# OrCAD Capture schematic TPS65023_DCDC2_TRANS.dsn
size Custom; title: TPS65023x Power Management IC (PMIC) With 3 DC/DCs,; rev: 1.0; note: Datasheet: SLVS670L     EVM: SLVU193; note: Synchronous Step Down Converter
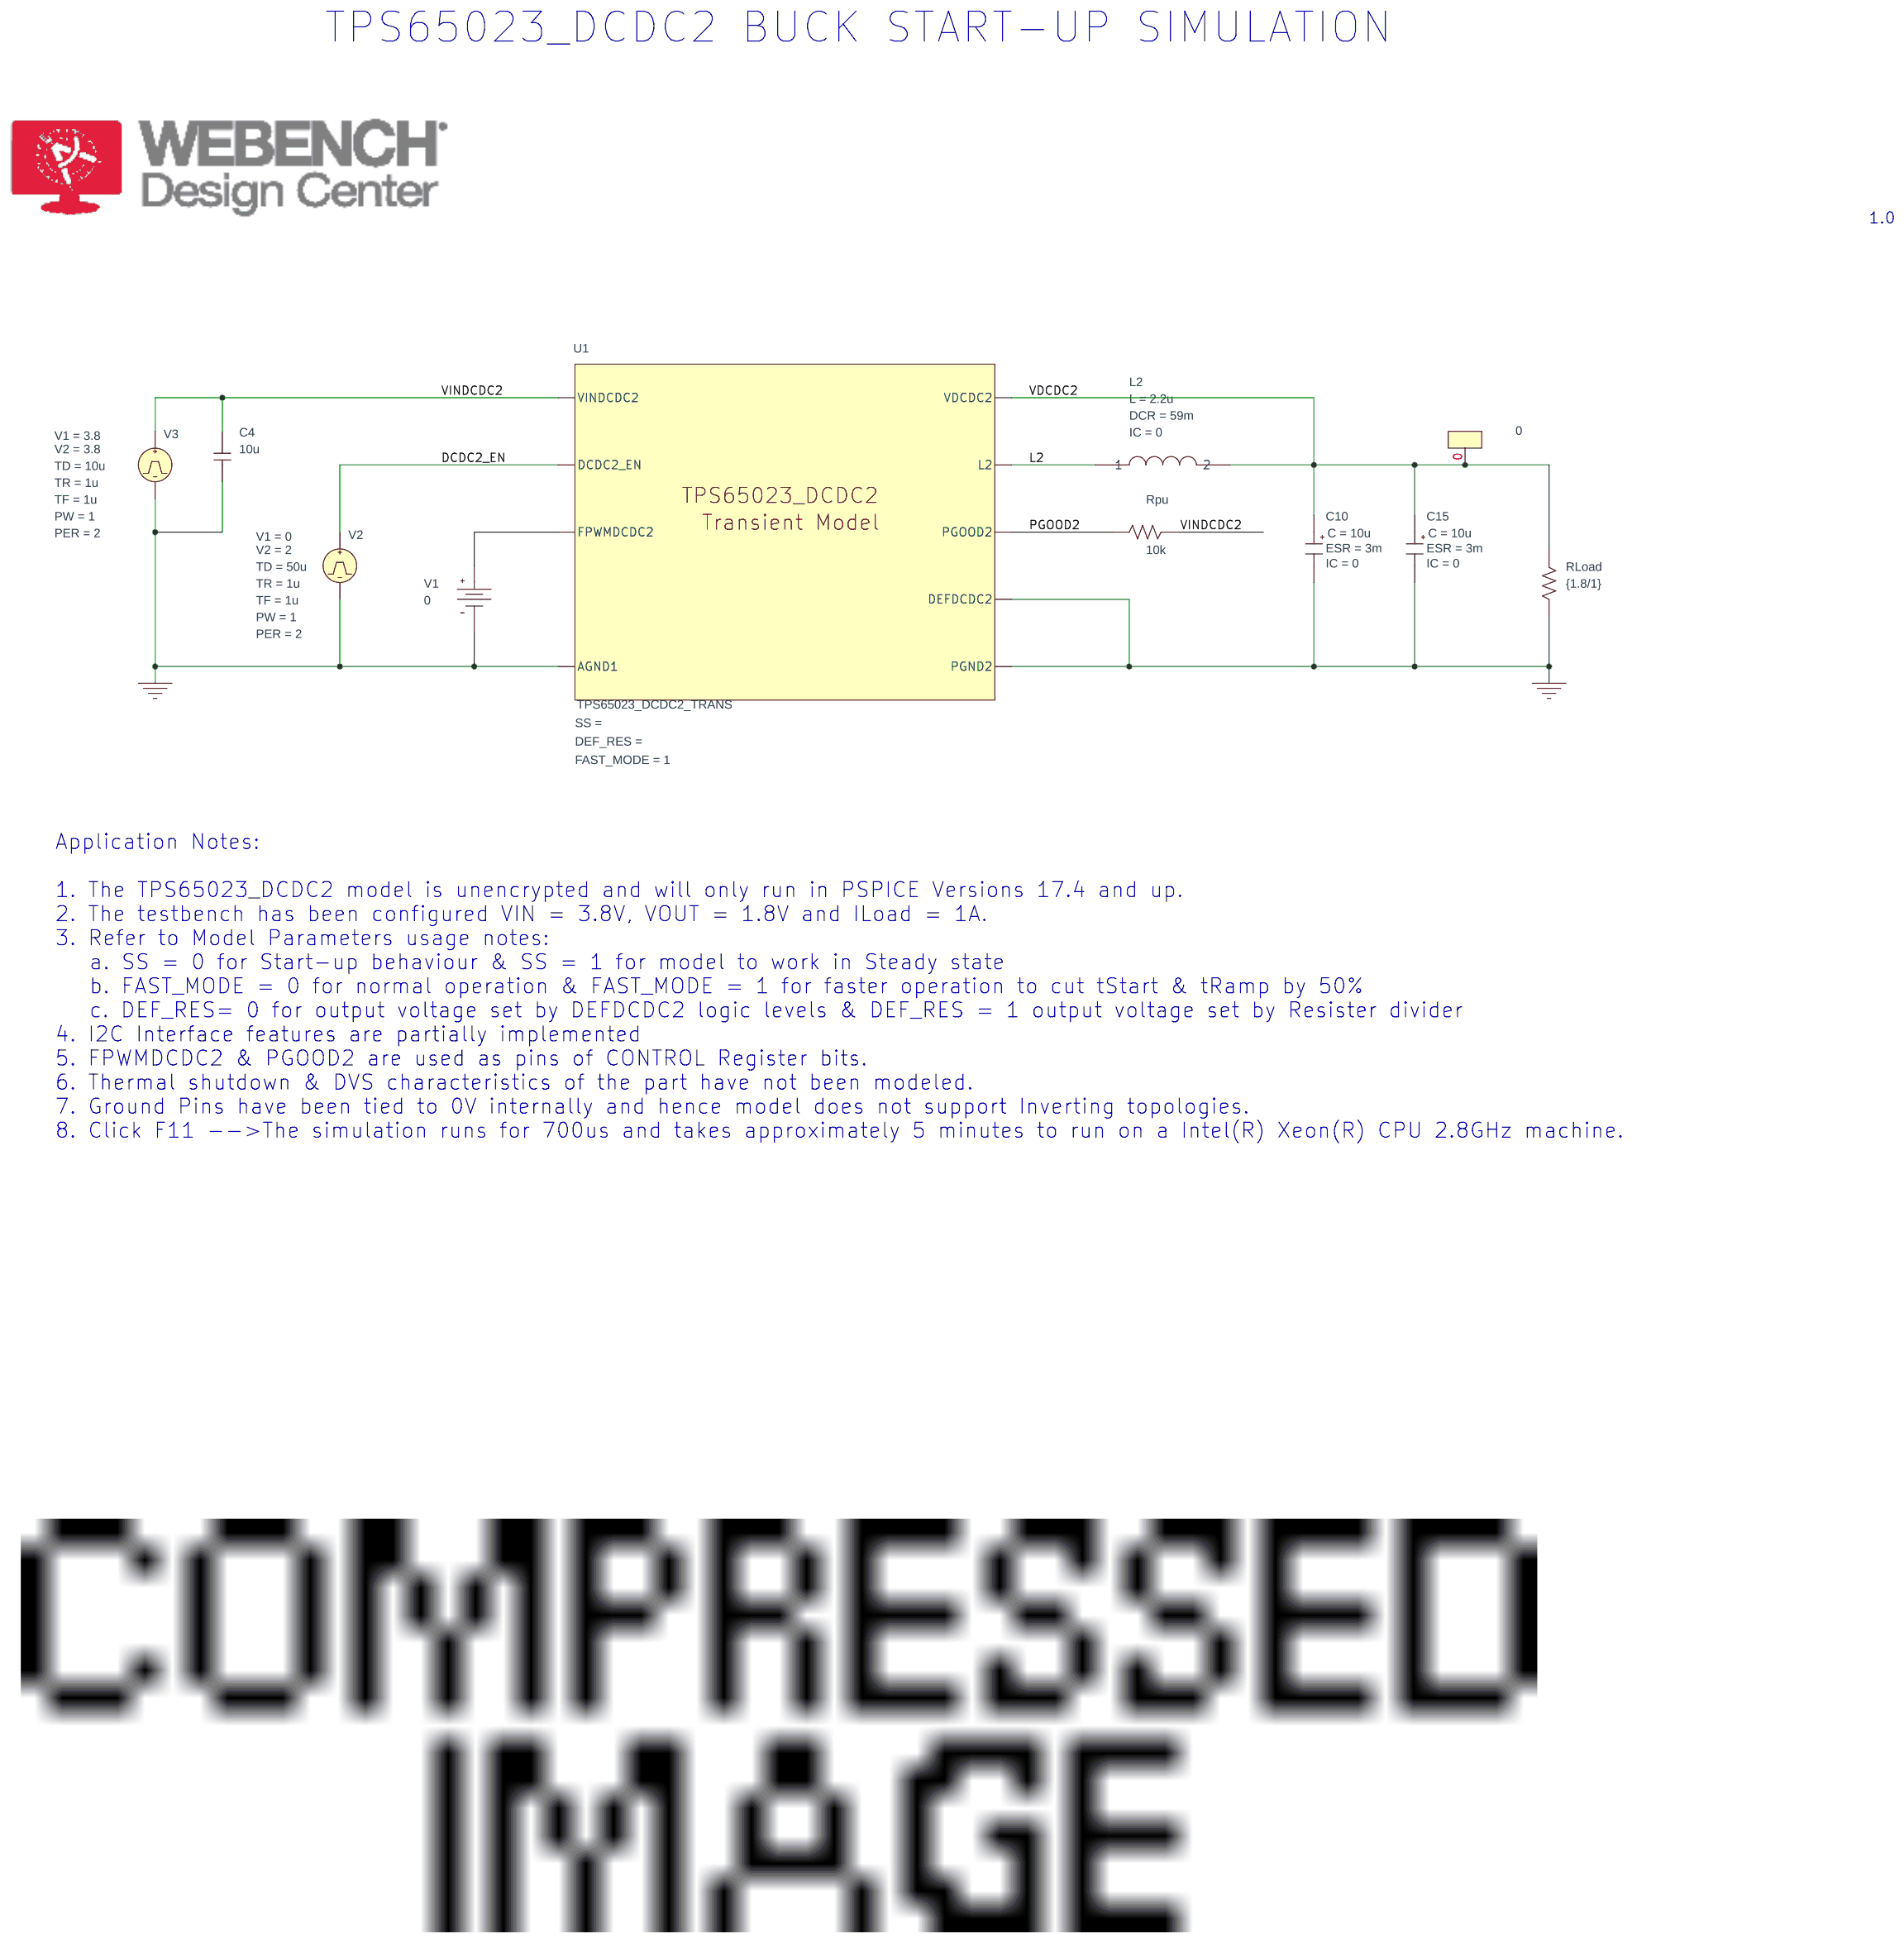
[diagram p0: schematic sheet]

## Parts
C4  10u  [RAD/CK05]
C10  CESR
C15  CESR
IC2  0
L2  LDCR
RLoad  {1.8/1}  [AX/RC05]
Rpu  10k  [AX/RC05]
U1  TPS65023_DCDC2_TRANS
V1  VDC
V2  VPULSE
V3  VPULSE

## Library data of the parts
C4 = C
C10 C15 = CESR_0: C: 10u; ESR: 3m; IC: 0; PSpiceTemplate: X^@REFDES %IN %OUT @MODEL PARAMS:  ?C|C=@C||C=100u|  ?ESR|ESR=@ESR||ESR=0.01| ?X|X=@X||X=2|  ?IC|IC=@IC||IC=2|; X: 1
IC2 = IC1
L2 = LDCR: DCR: 59m; IC: 0; L: 2.2u
RLoad Rpu = R
U1 = TPS65023_DCDC2_TRANS: FAST_MODE: 1
V1 = VDC: DC: 0
V2 = VPULSE: PER: 2; PW: 1; TD: 50u; TF: 1u; TR: 1u; V1: 0; V2: 2
V3 = VPULSE: PER: 2; PW: 1; TD: 10u; TF: 1u; TR: 1u; V1: 3.8; V2: 3.8

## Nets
VINDCDC2: C4.1 Rpu.1 U1.VINDCDC2 V3.1(+)
0: C4.2 C10.2(OUT) C15.2(OUT) RLoad.2 U1.AGND1 U1.DEFDCDC2 U1.PGND2 V1.1(-) V2.2(-) V3.2(-)
DCDC2_EN: U1.DCDC2_EN V2.1(+)
L2: L2.1 U1.L2
PGOOD2: Rpu.2 U1.PGOOD2
VDCDC2: C10.1(IN) C15.1(IN) IC2.0(+) L2.2 RLoad.1 U1.VDCDC2
N04438: U1.FPWMDCDC2 V1.0(+)

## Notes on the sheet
- TPS65023_DCDC2 BUCK START-UP SIMULATION
- 1.0
- Application Notes:
  1. The TPS65023_DCDC2 model is unencrypted and will only run in PSPICE Versions 17.4 and up.
  2. The testbench has been configured VIN = 3.8V, VOUT = 1.8V and ILoad = 1A.
  3. Refer to Model Parameters usage notes:
     a. SS = 0 for Start-up behaviour & SS = 1 for model to work in Steady state
     b. FAST_MODE = 0 for normal operation & FAST_MODE = 1 for faster operation to cut tStart & tRamp by 50%
     c. DEF_RES= 0 for output voltage set by DEFDCDC2 logic levels & DEF_RES = 1 output voltage set by Resister divider
  4. I2C Interface features are partially implemented
  5. FPWMDCDC2 & PGOOD2 are used as pins of CONTROL Register bits.
  6. Thermal shutdown & DVS characteristics of the part have not been modeled.
  7. Ground Pins have been tied to 0V internally and hence model does not support Inverting topologies.
  8. Click F11 -->The simulation runs for 700us and takes approximately 5 minutes to run on a Intel(R) Xeon(R) CPU 2.8GHz machine.
